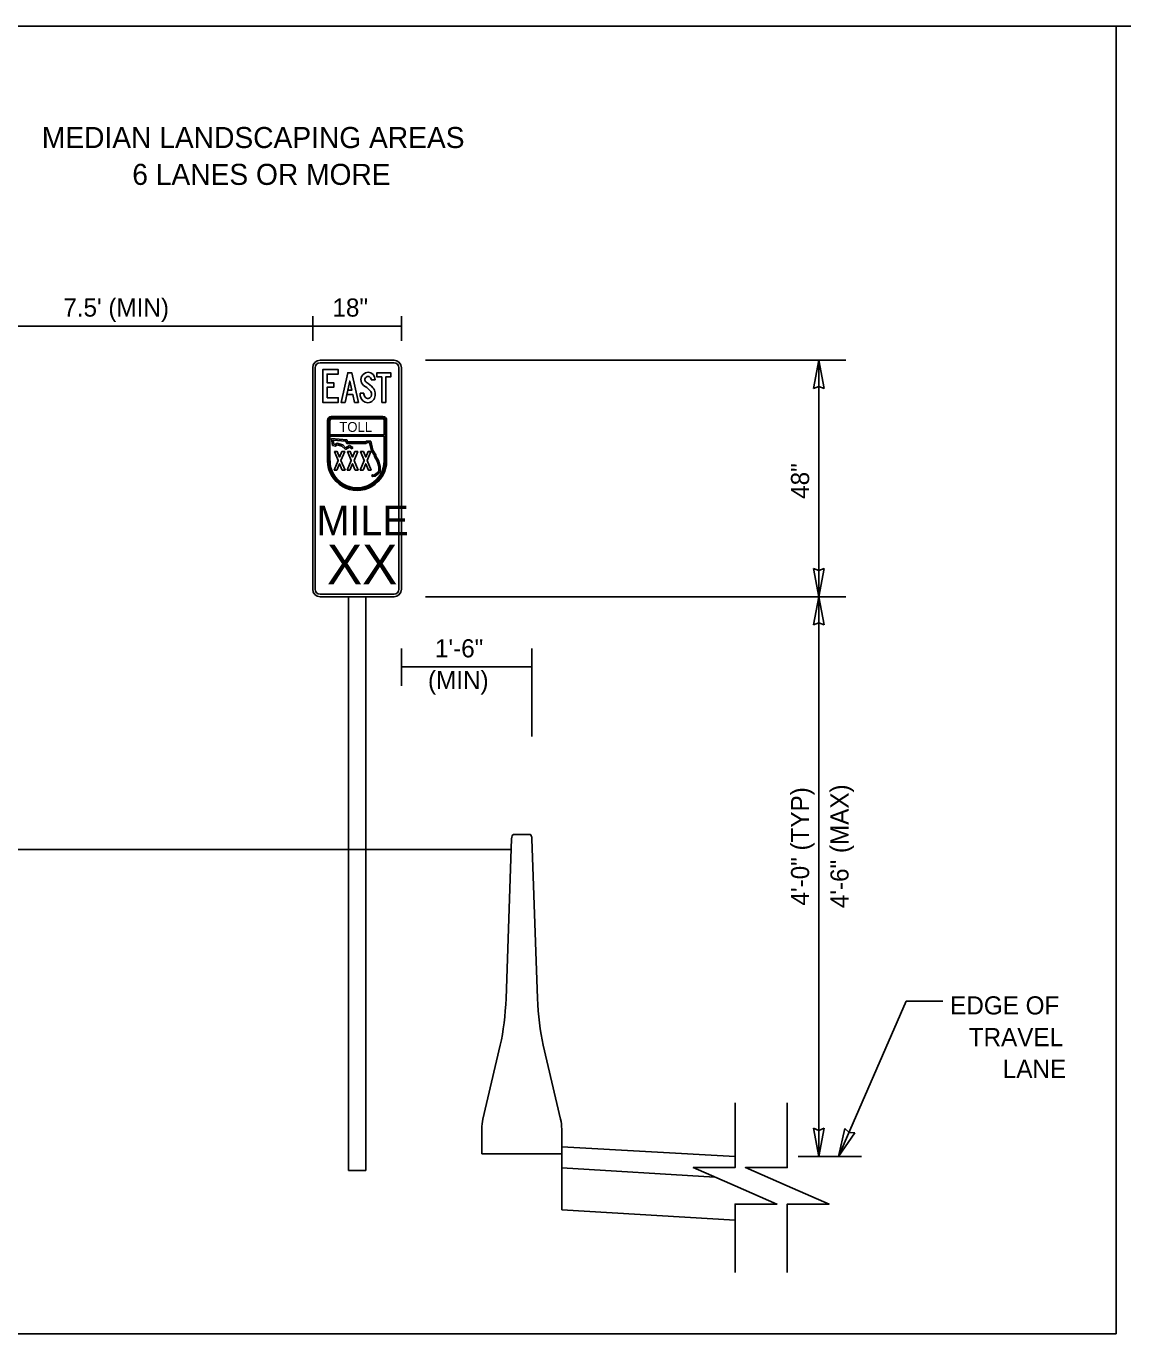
# Model space of a CAD drawing. Extents: x 57428 to 58066, y 11696 to 12105.
# Drawn here: x 57541.3 to 57710.6, y 11732.3 to 11934.3 of the extents above; entities that cross this region are included whole.
import ezdxf

# ---------------------------------------------------------------- set-up
doc = ezdxf.new("R2010")
doc.units = 0
for name, color, linetype in [('Default', 7, 'Continuous'), ('DimLines_dp', 7, 'Continuous'), ('NonPlottingEle_dp', 7, 'Continuous'), ('SignPanel', 7, 'Continuous'), ('TextMisc', 7, 'Continuous'), ('TextTables', 7, 'Continuous'), ('XSGrdLine_ex', 7, 'Continuous')]:
    doc.layers.add(name, color=color, linetype=linetype)

msp = doc.modelspace()

# ---------------------------------------------------------------- linework, layer by layer
at = {"layer": 'Default'}
for points in [[(57650.73, 11741.8), (57650.73, 11752.36), (57657.19, 11752.36), (57650.73, 11755.17), (57644.27, 11757.99), (57650.73, 11757.99), (57650.73, 11767.99)], [(57658.79, 11741.8), (57658.79, 11752.36), (57665.26, 11752.36), (57658.79, 11755.17), (57652.33, 11757.99), (57658.79, 11757.99), (57658.79, 11767.99)]]:
    msp.add_lwpolyline(points, dxfattribs=at)
at = {"layer": 'DimLines_dp'}
for p, q in [((57585.54, 11885.65), (57585.54, 11889.48)), ((57599.23, 11885.65), (57599.23, 11889.48)), ((57524.88, 11887.93), (57585.54, 11887.93)), ((57599.23, 11887.93), (57585.54, 11887.93)), ((57667.81, 11882.65), (57602.97, 11882.65)), ((57663.67, 11882.65), (57662.83, 11878.3)), ((57663.67, 11882.65), (57663.67, 11846.15)), ((57664.48, 11878.3), (57663.67, 11882.65)), ((57662.83, 11878.3), (57663.67, 11878.63)), ((57663.67, 11878.63), (57664.48, 11878.3)), ((57663.67, 11852.14), (57663.67, 11759.71)), ((57663.67, 11850.17), (57662.86, 11850.5)), ((57662.86, 11850.5), (57663.67, 11846.15)), ((57663.67, 11850.17), (57662.86, 11850.5)), ((57662.86, 11850.5), (57663.67, 11846.15)), ((57663.67, 11846.15), (57664.51, 11850.5)), ((57664.51, 11850.5), (57663.67, 11850.17)), ((57663.67, 11846.15), (57664.51, 11850.5)), ((57664.51, 11850.5), (57663.67, 11850.17)), ((57667.81, 11846.15), (57602.97, 11846.15)), ((57663.67, 11846.15), (57662.83, 11841.8)), ((57664.48, 11841.8), (57663.67, 11846.15)), ((57662.83, 11841.8), (57663.67, 11842.13)), ((57663.67, 11842.13), (57664.48, 11841.8)), ((57599.23, 11832.39), (57599.23, 11838.14)), ((57619.37, 11824.54), (57619.37, 11838.14)), ((57619.37, 11835.3), (57599.23, 11835.3)), ((57677.15, 11783.68), (57666.72, 11759.71)), ((57682.8, 11783.68), (57677.15, 11783.68)), ((57663.67, 11763.73), (57662.86, 11764.06)), ((57662.86, 11764.06), (57663.67, 11759.71)), ((57663.67, 11759.71), (57664.51, 11764.06)), ((57664.51, 11764.06), (57663.67, 11763.73)), ((57666.72, 11759.71), (57667.69, 11764.03)), ((57669.2, 11763.37), (57666.72, 11759.71)), ((57667.69, 11764.03), (57668.33, 11763.39)), ((57668.33, 11763.39), (57669.2, 11763.37)), ((57660.46, 11759.71), (57670.24, 11759.71))]:
    msp.add_line(p, q, dxfattribs=at)
at = {"layer": 'NonPlottingEle_dp'}
for p, q in [((57591.06, 11807.11), (57591.06, 11846.15)), ((57593.72, 11807.11), (57593.72, 11846.15)), ((57591.06, 11757.53), (57591.06, 11807.11)), ((57593.72, 11757.53), (57593.72, 11807.11)), ((57593.72, 11757.53), (57591.06, 11757.53))]:
    msp.add_line(p, q, dxfattribs=at)
at = {"layer": 'SignPanel'}
for p, q in [((57594.58, 11879.64), (57595.16, 11879.64)), ((57594.58, 11879.64), (57595.16, 11879.64)), ((57594.58, 11879.64), (57595.16, 11879.64)), ((57593.44, 11877.6), (57592.85, 11877.6)), ((57593.44, 11877.6), (57592.85, 11877.6)), ((57593.44, 11877.6), (57592.85, 11877.6)), ((57588.4, 11873.98), (57596.38, 11873.98)), ((57587.83, 11867.13), (57587.83, 11873.41)), ((57588.02, 11867.13), (57588.02, 11873.41)), ((57588.2, 11871.13), (57588.2, 11873.41)), ((57588.4, 11873.79), (57596.38, 11873.79)), ((57588.4, 11873.6), (57596.38, 11873.6)), ((57596.57, 11871.13), (57596.57, 11873.41)), ((57596.76, 11867.13), (57596.76, 11873.41)), ((57596.95, 11867.13), (57596.95, 11873.41)), ((57588.2, 11871.13), (57596.57, 11871.13)), ((57588.2, 11867.13), (57588.2, 11870.94)), ((57588.2, 11870.94), (57596.57, 11870.94)), ((57588.59, 11869.48), (57588.42, 11870.57)), ((57588.42, 11870.57), (57590.8, 11870.39)), ((57590.64, 11870.17), (57588.69, 11870.32)), ((57588.69, 11870.32), (57588.79, 11869.69)), ((57589.68, 11870.23), (57589.68, 11870.23)), ((57590.78, 11869.81), (57590.64, 11870.17)), ((57590.8, 11870.39), (57590.93, 11870.04)), ((57590.93, 11870.04), (57593.66, 11870.04)), ((57593.66, 11870.04), (57593.77, 11870.19)), ((57593.77, 11870.19), (57594.5, 11870.19)), ((57593.89, 11869.97), (57593.79, 11869.81)), ((57594.32, 11869.97), (57593.89, 11869.97)), ((57594.62, 11868.67), (57594.32, 11869.97)), ((57594.5, 11870.19), (57594.83, 11868.76)), ((57596.57, 11867.13), (57596.57, 11870.94)), ((57589.04, 11869.42), (57588.59, 11869.48)), ((57588.79, 11869.69), (57588.98, 11869.66)), ((57588.98, 11869.66), (57589.25, 11869.88)), ((57589.29, 11869.62), (57589.04, 11869.42)), ((57589.25, 11869.88), (57590.17, 11869.58)), ((57590.05, 11869.37), (57589.29, 11869.62)), ((57590.59, 11868.88), (57590.05, 11869.37)), ((57590.17, 11869.58), (57590.62, 11869.16)), ((57591.22, 11869.25), (57590.59, 11868.88)), ((57590.62, 11869.16), (57591.23, 11869.52)), ((57593.79, 11869.81), (57590.78, 11869.81)), ((57591.6, 11868.99), (57591.22, 11869.25)), ((57591.23, 11869.52), (57591.73, 11869.18)), ((57591.73, 11869.18), (57591.6, 11868.99)), ((57595.06, 11867.97), (57594.62, 11868.67)), ((57594.83, 11868.76), (57595.29, 11868.04)), ((57595.06, 11867.79), (57595.06, 11867.97)), ((57595.29, 11868.04), (57595.29, 11867.85)), ((57595.48, 11867.09), (57595.06, 11867.79)), ((57595.29, 11867.85), (57595.7, 11867.18)), ((57595.72, 11866.23), (57595.48, 11867.09)), ((57595.7, 11867.18), (57595.95, 11866.26)), ((57595.72, 11865.5), (57595.72, 11866.23)), ((57595.95, 11866.26), (57595.95, 11865.39)), ((57594.61, 11864.85), (57594.74, 11865.04)), ((57594.84, 11864.69), (57594.61, 11864.85)), ((57594.74, 11865.04), (57594.89, 11864.94)), ((57595.2, 11864.78), (57594.84, 11864.69)), ((57594.89, 11864.94), (57595.09, 11864.99)), ((57595.09, 11864.99), (57595.72, 11865.5)), ((57595.95, 11865.39), (57595.2, 11864.78))]:
    msp.add_line(p, q, dxfattribs=at)
for points in [[(57586.68, 11882.65), (57598.09, 11882.65)], [(57586.68, 11882.27), (57598.09, 11882.27)], [(57585.54, 11847.29), (57585.54, 11881.51)], [(57585.92, 11847.29), (57585.92, 11881.51)], [(57598.85, 11881.51), (57598.85, 11847.29)], [(57599.23, 11881.51), (57599.23, 11847.29)], [(57598.09, 11846.53), (57586.68, 11846.53)], [(57598.09, 11846.15), (57586.68, 11846.15)]]:
    msp.add_lwpolyline(points, dxfattribs=at)
for points in [[(57587.75, 11876.87), (57587.75, 11878.49), (57588.77, 11878.49), (57588.77, 11879.2), (57587.75, 11879.2), (57587.75, 11880.52), (57589.47, 11880.52), (57589.47, 11881.23), (57587.09, 11881.23), (57587.09, 11876.16), (57589.47, 11876.16), (57589.47, 11876.87)], [(57587.75, 11876.87), (57587.75, 11878.49), (57588.77, 11878.49), (57588.77, 11879.2), (57587.75, 11879.2), (57587.75, 11880.52), (57589.47, 11880.52), (57589.47, 11881.23), (57587.09, 11881.23), (57587.09, 11876.16), (57589.47, 11876.16), (57589.47, 11876.87)], [(57587.75, 11876.87), (57587.75, 11878.49), (57588.77, 11878.49), (57588.77, 11879.2), (57587.75, 11879.2), (57587.75, 11880.52), (57589.47, 11880.52), (57589.47, 11881.23), (57587.09, 11881.23), (57587.09, 11876.16), (57589.47, 11876.16), (57589.47, 11876.87)], [(57591.72, 11877.39), (57591.99, 11876.16), (57592.59, 11876.16), (57591.57, 11880.74), (57590.94, 11880.74), (57589.92, 11876.16), (57590.53, 11876.16), (57590.8, 11877.39)], [(57590.95, 11878.03), (57590.8, 11877.39), (57591.72, 11877.39), (57591.99, 11876.16), (57592.59, 11876.16), (57591.57, 11880.74), (57590.94, 11880.74), (57589.92, 11876.16), (57590.53, 11876.16), (57591.26, 11879.44), (57591.57, 11878.03)], [(57590.95, 11878.03), (57590.8, 11877.39), (57591.72, 11877.39), (57591.99, 11876.16), (57592.59, 11876.16), (57591.57, 11880.74), (57590.94, 11880.74), (57589.92, 11876.16), (57590.53, 11876.16), (57591.26, 11879.44), (57591.57, 11878.03)], [(57596.23, 11880.1), (57595.45, 11880.1), (57595.45, 11880.74), (57597.59, 11880.74), (57597.59, 11880.1), (57596.81, 11880.1), (57596.81, 11876.16), (57596.23, 11876.16)], [(57596.23, 11880.1), (57595.45, 11880.1), (57595.45, 11880.74), (57597.59, 11880.74), (57597.59, 11880.1), (57596.81, 11880.1), (57596.81, 11876.16), (57596.23, 11876.16)], [(57596.23, 11880.1), (57595.45, 11880.1), (57595.45, 11880.74), (57597.59, 11880.74), (57597.59, 11880.1), (57596.81, 11880.1), (57596.81, 11876.16), (57596.23, 11876.16)], [(57591.26, 11879.44), (57591.57, 11878.03), (57590.95, 11878.03)], [(57589.28, 11865.71), (57589.69, 11866.69), (57590.09, 11865.71), (57590.52, 11865.71), (57589.9, 11867.2), (57590.47, 11868.57), (57590.04, 11868.57), (57589.69, 11867.71), (57589.33, 11868.57), (57588.9, 11868.57), (57589.47, 11867.2), (57588.85, 11865.71)], [(57591.29, 11865.71), (57591.7, 11866.69), (57592.11, 11865.71), (57592.54, 11865.71), (57591.91, 11867.2), (57592.49, 11868.57), (57592.06, 11868.57), (57591.7, 11867.71), (57591.34, 11868.57), (57590.92, 11868.57), (57591.49, 11867.2), (57590.87, 11865.71)], [(57593.31, 11865.71), (57593.72, 11866.69), (57594.13, 11865.71), (57594.55, 11865.71), (57593.93, 11867.2), (57594.5, 11868.57), (57594.08, 11868.57), (57593.72, 11867.71), (57593.36, 11868.57), (57592.93, 11868.57), (57593.5, 11867.2), (57592.88, 11865.71)]]:
    msp.add_lwpolyline(points, close=True, dxfattribs=at)
for centre, radius, start, end in [((57586.68, 11881.51), 1.14, 90, 180), ((57586.68, 11881.51), 0.76, 90, 180), ((57598.09, 11881.51), 1.14, 0, 90), ((57598.09, 11881.51), 0.76, 0, 90), ((57586.68, 11847.29), 1.14, 180, 270), ((57586.68, 11847.29), 0.76, 180, 270), ((57598.09, 11847.29), 1.14, 270, 360), ((57598.09, 11847.29), 0.76, 270, 360)]:
    msp.add_arc(centre, radius, start, end, dxfattribs=at)
for centre, major_axis, ratio, start_param, end_param in [((57594.07, 11879.61), (0, 1.19), 0.91923, 4.736267, 7.790596), ((57594.07, 11879.61), (0, 1.19), 0.91923, 4.736267, 7.790596), ((57594.07, 11879.61), (0, 1.19), 0.91923, 4.736267, 7.790596), ((57594.07, 11879.6), (0, 0.558), 0.91923, 4.786904, 7.140738), ((57594.07, 11879.6), (0, 0.558), 0.91923, 4.786904, 7.140738), ((57594.07, 11879.6), (0, 0.558), 0.91923, 4.786904, 7.140738), ((57593.96, 11879.65), (0, 1.07), 0.91923, 1.534831, 2.511766), ((57593.96, 11879.65), (0, 1.07), 0.91923, 1.534831, 2.511766), ((57593.96, 11879.65), (0, 1.07), 0.91923, 1.534831, 2.511766), ((57591.36, 11874.71), (0, 4.63), 0.91923, 5.515137, 5.786988), ((57591.36, 11874.71), (0, 4.63), 0.91923, 5.515137, 5.786988), ((57591.36, 11874.71), (0, 4.63), 0.91923, 5.515137, 5.786988), ((57594, 11879.67), (0, 0.46), 0.91923, 0.87378, 2.656959), ((57594, 11879.67), (0, 0.46), 0.91923, 0.87378, 2.656959), ((57594, 11879.67), (0, 0.46), 0.91923, 0.87378, 2.656959), ((57591.87, 11875.41), (0, 4.39), 0.91923, 5.462886, 5.782242), ((57591.87, 11875.41), (0, 4.39), 0.91923, 5.462886, 5.782242), ((57591.87, 11875.41), (0, 4.39), 0.91923, 5.462886, 5.782242), ((57593.88, 11877.41), (0, 0.792), 0.91923, 4.254409, 5.632398), ((57593.88, 11877.41), (0, 0.792), 0.91923, 4.254409, 5.632398), ((57593.88, 11877.41), (0, 0.792), 0.91923, 4.254409, 5.632398), ((57593.89, 11877.41), (0, 1.42), 0.91923, 4.260987, 5.485755), ((57593.89, 11877.41), (0, 1.42), 0.91923, 4.260987, 5.485755), ((57593.89, 11877.41), (0, 1.42), 0.91923, 4.260987, 5.485755), ((57594.22, 11877.53), (0, 1.5), 0.91923, 1.526364, 2.701682), ((57594.22, 11877.53), (0, 1.5), 0.91923, 1.526364, 2.701682), ((57594.22, 11877.53), (0, 1.5), 0.91923, 1.526364, 2.701682), ((57594.28, 11877.56), (0, 0.911), 0.91923, 1.524757, 2.28214), ((57594.28, 11877.56), (0, 0.911), 0.91923, 1.524757, 2.28214), ((57594.28, 11877.56), (0, 0.911), 0.91923, 1.524757, 2.28214), ((57594.04, 11877.35), (0, 1.24), 0.91923, 2.786047, 4.251692), ((57594.04, 11877.35), (0, 1.24), 0.91923, 2.786047, 4.251692), ((57594.04, 11877.35), (0, 1.24), 0.91923, 2.786047, 4.251692), ((57594.06, 11877.33), (0, 0.581), 0.91923, 2.261787, 4.23006), ((57594.06, 11877.33), (0, 0.581), 0.91923, 2.261787, 4.23006), ((57594.06, 11877.33), (0, 0.581), 0.91923, 2.261787, 4.23006), ((57588.4, 11873.41), (0, 0.57), 0.9997, 0, 1.570796), ((57596.38, 11873.41), (0, 0.57), 0.9997, 4.712389, 6.283185), ((57588.4, 11873.41), (0, 0.38), 0.9997, 0, 1.570796), ((57588.4, 11873.41), (0, 0.19), 0.9997, 0, 1.570796), ((57596.38, 11873.41), (0, 0.38), 0.9997, 4.712389, 6.283185), ((57596.38, 11873.41), (0, 0.19), 0.9997, 4.712389, 6.283185), ((57592.39, 11867.13), (0, -4.56), 0.9997, 4.712389, 7.853982), ((57592.39, 11867.13), (0, -4.37), 0.9997, 4.712389, 7.853982), ((57592.39, 11867.13), (0, -4.18), 0.9997, 4.712389, 7.853982)]:
    msp.add_ellipse(centre, major_axis=major_axis, ratio=ratio, start_param=start_param, end_param=end_param, dxfattribs=at)
at = {"layer": 'TextMisc'}
msp.add_line((58065.89, 11934.25), (57709.55, 11934.25), dxfattribs=at)
msp.add_lwpolyline([(57449.89, 11934.25), (57709.55, 11934.25), (57709.55, 11732.32), (57449.89, 11732.32)], close=True, dxfattribs=at)
at = {"layer": 'XSGrdLine_ex'}
for p, q in [((57616.5, 11809.43), (57619.11, 11809.43)), ((57615.38, 11784.12), (57616.24, 11808.74)), ((57620.23, 11784.12), (57619.37, 11808.74)), ((57494.48, 11807.11), (57616.18, 11807.11)), ((57611.81, 11765.45), (57614.48, 11776.9)), ((57623.8, 11765.45), (57621.13, 11776.9)), ((57611.64, 11760.13), (57611.64, 11763.91)), ((57623.97, 11760.13), (57623.97, 11763.91)), ((57623.97, 11761.2), (57623.97, 11760.13)), ((57650.73, 11759.71), (57623.97, 11761.2)), ((57611.64, 11760.13), (57623.97, 11760.13)), ((57623.97, 11760.13), (57623.97, 11751.48)), ((57623.97, 11757.95), (57647.62, 11756.53)), ((57623.97, 11751.48), (57650.73, 11749.87))]:
    msp.add_line(p, q, dxfattribs=at)
for centre, major_axis, start_param, end_param in [((57616.5, 11808.66), (0, 0.77), 0, 1.465919), ((57619.11, 11808.66), (0, 0.77), 4.817266, 6.283185), ((57610.27, 11785.73), (0, -15.4), 0.96007, 1.465919), ((57625.34, 11785.73), (0, -15.4), 4.817266, 5.323115), ((57612.54, 11763.91), (0, 2.7), 0.96007, 1.570796), ((57623.07, 11763.91), (0, 2.7), 4.712389, 5.323115)]:
    msp.add_ellipse(centre, major_axis=major_axis, ratio=0.333333, start_param=start_param, end_param=end_param, dxfattribs=at)

# ---------------------------------------------------------------- texts
at = {"layer": 'DimLines_dp'}
for s, p in [("7.5' (MIN)", (57547.03, 11889.4)), ('18"', (57588.58, 11889.4)), ('1\'-6"', (57604.41, 11836.78)), ('(MIN)', (57603.33, 11831.88)), ('EDGE OF ', (57683.94, 11781.64)), ('TRAVEL ', (57686.81, 11776.74)), ('LANE', (57692.07, 11771.84))]:
    msp.add_text(s, height=2.8, dxfattribs=at).set_placement(p)
for s, p in [('48"', (57662.17, 11861.26)), ('4\'-0" (TYP)', (57662.17, 11798.46)), ('4\'-6" (MAX)', (57668.26, 11798.06))]:
    msp.add_text(s, height=2.8, rotation=90, dxfattribs=at).set_placement(p)
at = {"layer": 'SignPanel'}
for s, height, p in [('TOLL', 1.519, (57589.63, 11871.6)), ('MILE', 4.562, (57586.13, 11855.65)), ('XX', 6.083, (57587.74, 11848.08))]:
    msp.add_text(s, height=height, dxfattribs=at).set_placement(p)
at = {"layer": 'TextTables'}
for s, p in [('MEDIAN LANDSCAPING AREAS', (57543.72, 11915.43)), ('6 LANES OR MORE', (57557.68, 11909.74))]:
    msp.add_text(s, height=3.2524, dxfattribs=at).set_placement(p)

doc.saveas('drawing.dxf')
